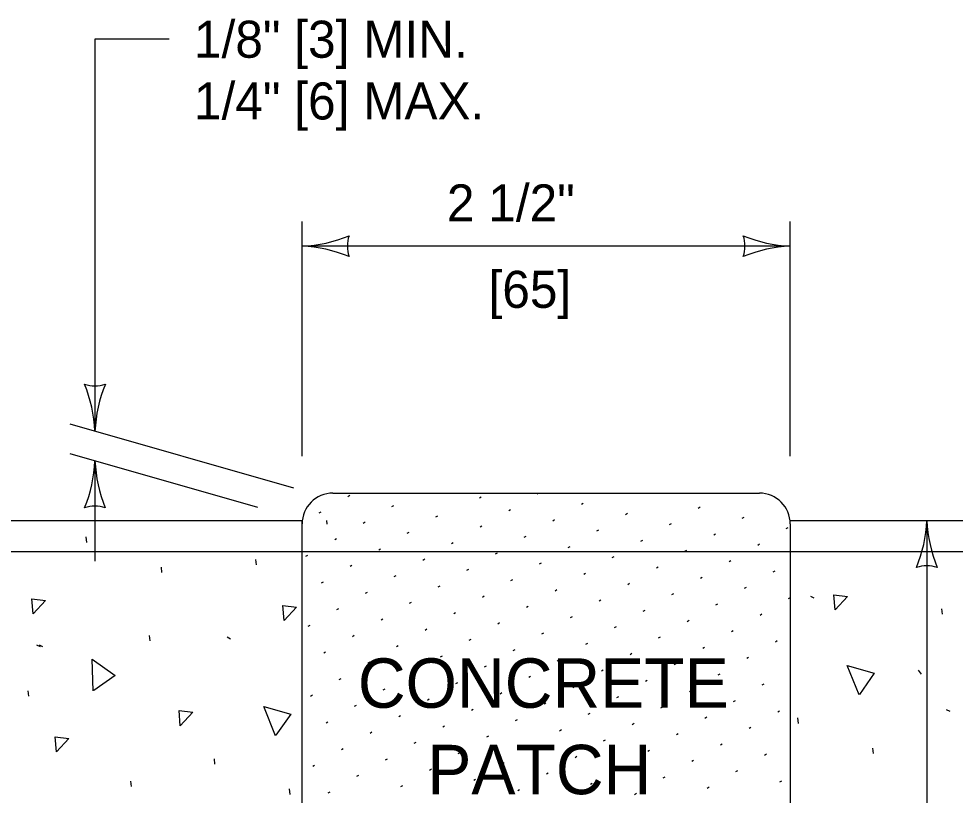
# Model space of a CAD drawing. Extents: x 49991.4 to 50021, y 49987.6 to 50011.4.
# Drawn here: x 50003.117 to 50004.633, y 49990.433 to 49991.691 of the extents above; entities that cross this region are included whole.
import ezdxf

# ---------------------------------------------------------------- set-up
doc = ezdxf.new("R2010")
doc.units = 0
for name, color, linetype in [('Level 1', 7, 'Continuous'), ('Level 15', 7, 'Continuous'), ('Level 2', 7, 'Continuous'), ('Level 3', 7, 'Continuous'), ('Level 4', 7, 'Continuous'), ('Level 6', 7, 'Continuous')]:
    doc.layers.add(name, color=color, linetype=linetype)

msp = doc.modelspace()

# ---------------------------------------------------------------- linework, layer by layer
at = {"layer": 'Level 1'}
for p, q in [((50002.5169, 49990.8781), (50003.5758, 49990.8781)), ((50004.3657, 49990.8781), (50005.421, 49990.8781)), ((50002.5169, 49990.8281), (50005.421, 49990.8281))]:
    msp.add_line(p, q, dxfattribs=at)
at = {"layer": 'Level 15'}
msp.add_line((50004.587, 49990.8781), (50004.587, 49989.7448), dxfattribs=at)
at = {"layer": 'Level 3'}
for p, q in [((50003.2406, 49991.6576), (50003.2406, 49991.0229)), ((50003.3609, 49991.6576), (50003.2406, 49991.6576)), ((50003.5758, 49990.9825), (50003.5758, 49991.3625)), ((50004.366, 49990.9825), (50004.366, 49991.3625)), ((50004.366, 49991.3225), (50003.5758, 49991.3225)), ((50003.5623, 49990.9305), (50003.2006, 49991.0344)), ((50003.5042, 49990.899), (50003.2006, 49990.9862)), ((50003.2406, 49990.9724), (50003.2406, 49990.8124)), ((50003.6499, 49990.9172), (50003.6529, 49990.919)), ((50003.8629, 49990.9148), (50003.8659, 49990.9165)), ((50003.9566, 49990.9211), (50003.959, 49990.9225)), ((50003.7212, 49990.9007), (50003.7243, 49990.9024)), ((50004.0279, 49990.9046), (50004.031, 49990.9063)), ((50004.217, 49990.8982), (50004.22, 49990.9)), ((50003.6036, 49990.8905), (50003.6066, 49990.8922)), ((50003.7926, 49990.8841), (50003.7956, 49990.8859)), ((50003.9103, 49990.8943), (50003.9133, 49990.8961)), ((50004.0993, 49990.888), (50004.1023, 49990.8898)), ((50004.2883, 49990.8817), (50004.2913, 49990.8834)), ((50003.6749, 49990.8739), (50003.6779, 49990.8757)), ((50003.8639, 49990.8676), (50003.867, 49990.8693)), ((50003.9816, 49990.8778), (50003.9846, 49990.8795)), ((50004.1706, 49990.8715), (50004.1736, 49990.8732)), ((50003.7462, 49990.8574), (50003.7493, 49990.8591)), ((50003.9353, 49990.851), (50003.9383, 49990.8528)), ((50004.0529, 49990.8613), (50004.056, 49990.863)), ((50004.242, 49990.8549), (50004.245, 49990.8567)), ((50004.3596, 49990.8651), (50004.3627, 49990.8669)), ((50003.6286, 49990.8472), (50003.6316, 49990.8489)), ((50003.8176, 49990.8408), (50003.8206, 49990.8426)), ((50004.1243, 49990.8447), (50004.1273, 49990.8465)), ((50004.3133, 49990.8384), (50004.3163, 49990.8401)), ((50003.5822, 49990.8204), (50003.5853, 49990.8222)), ((50003.6999, 49990.8306), (50003.7029, 49990.8324)), ((50003.8889, 49990.8243), (50003.892, 49990.826)), ((50004.0066, 49990.8345), (50004.0096, 49990.8362)), ((50004.1956, 49990.8282), (50004.1986, 49990.8299)), ((50003.7712, 49990.8141), (50003.7743, 49990.8158)), ((50003.9603, 49990.8077), (50003.9633, 49990.8095)), ((50004.0779, 49990.818), (50004.081, 49990.8197)), ((50004.267, 49990.8116), (50004.27, 49990.8134)), ((50003.6536, 49990.8039), (50003.6566, 49990.8056)), ((50003.8426, 49990.7975), (50003.8456, 49990.7993)), ((50004.0316, 49990.7912), (50004.0346, 49990.7929)), ((50004.1493, 49990.8014), (50004.1523, 49990.8032)), ((50004.3383, 49990.7951), (50004.3413, 49990.7968)), ((50003.6072, 49990.7771), (50003.6103, 49990.7789)), ((50003.7249, 49990.7873), (50003.7279, 49990.7891)), ((50003.9139, 49990.781), (50003.917, 49990.7827)), ((50004.1029, 49990.7746), (50004.106, 49990.7764)), ((50004.2206, 49990.7849), (50004.2236, 49990.7866)), ((50003.6786, 49990.7606), (50003.6816, 49990.7623)), ((50003.7962, 49990.7708), (50003.7993, 49990.7725)), ((50003.9853, 49990.7644), (50003.9883, 49990.7662)), ((50004.292, 49990.7683), (50004.295, 49990.7701)), ((50003.8676, 49990.7542), (50003.8706, 49990.756)), ((50004.0566, 49990.7479), (50004.0596, 49990.7496)), ((50004.1743, 49990.7581), (50004.1773, 49990.7599)), ((50004.3633, 49990.7518), (50004.3654, 49990.753)), ((50003.6322, 49990.7338), (50003.6353, 49990.7356)), ((50003.7499, 49990.744), (50003.7529, 49990.7458)), ((50003.9389, 49990.7377), (50003.942, 49990.7394)), ((50004.1279, 49990.7313), (50004.131, 49990.7331)), ((50004.2456, 49990.7416), (50004.2486, 49990.7433)), ((50003.7036, 49990.7173), (50003.7066, 49990.719)), ((50003.8212, 49990.7275), (50003.8243, 49990.7292)), ((50004.0103, 49990.7211), (50004.0133, 49990.7229)), ((50004.1993, 49990.7148), (50004.2023, 49990.7166)), ((50004.317, 49990.725), (50004.32, 49990.7268)), ((50003.7749, 49990.7007), (50003.7779, 49990.7025)), ((50003.8926, 49990.7109), (50003.8956, 49990.7127)), ((50004.0816, 49990.7046), (50004.0846, 49990.7063)), ((50003.6572, 49990.6905), (50003.6603, 49990.6923)), ((50003.8462, 49990.6842), (50003.8493, 49990.6859)), ((50003.9639, 49990.6944), (50003.967, 49990.6961)), ((50004.1529, 49990.688), (50004.156, 49990.6898)), ((50004.2706, 49990.6983), (50004.2736, 49990.7)), ((50003.7286, 49990.674), (50003.7316, 49990.6757)), ((50004.0353, 49990.6778), (50004.0383, 49990.6796)), ((50004.2243, 49990.6715), (50004.2273, 49990.6732)), ((50004.342, 49990.6817), (50004.345, 49990.6835)), ((50003.6109, 49990.6638), (50003.6139, 49990.6655)), ((50003.7999, 49990.6574), (50003.8029, 49990.6592)), ((50003.9176, 49990.6676), (50003.9206, 49990.6694)), ((50004.1066, 49990.6613), (50004.1096, 49990.663)), ((50004.2956, 49990.655), (50004.2986, 49990.6567)), ((50003.6822, 49990.6472), (50003.6853, 49990.649)), ((50003.8712, 49990.6409), (50003.8743, 49990.6426)), ((50003.9889, 49990.6511), (50003.992, 49990.6528)), ((50004.1779, 49990.6447), (50004.181, 49990.6465)), ((50003.7536, 49990.6307), (50003.7566, 49990.6324)), ((50003.9426, 49990.6243), (50003.9456, 49990.6261)), ((50004.0603, 49990.6345), (50004.0633, 49990.6363)), ((50004.2493, 49990.6282), (50004.2523, 49990.6299)), ((50003.6359, 49990.6205), (50003.6389, 49990.6222)), ((50003.8249, 49990.6141), (50003.8279, 49990.6159)), ((50004.1316, 49990.618), (50004.1346, 49990.6197)), ((50004.3206, 49990.6117), (50004.3236, 49990.6134)), ((50003.5896, 49990.5937), (50003.5926, 49990.5955)), ((50003.7072, 49990.6039), (50003.7103, 49990.6057)), ((50003.8962, 49990.5976), (50003.8993, 49990.5993)), ((50004.0139, 49990.6078), (50004.017, 49990.6095)), ((50004.2029, 49990.6014), (50004.206, 49990.6032)), ((50003.7786, 49990.5874), (50003.7816, 49990.5891)), ((50003.9676, 49990.581), (50003.9706, 49990.5828)), ((50004.0853, 49990.5912), (50004.0883, 49990.593)), ((50004.2743, 49990.5849), (50004.2773, 49990.5866)), ((50003.6609, 49990.5772), (50003.6639, 49990.5789)), ((50003.8499, 49990.5708), (50003.8529, 49990.5726)), ((50004.0389, 49990.5645), (50004.042, 49990.5662)), ((50004.1566, 49990.5747), (50004.1596, 49990.5764)), ((50004.3456, 49990.5683), (50004.3486, 49990.5701)), ((50003.6146, 49990.5504), (50003.6176, 49990.5522)), ((50003.7322, 49990.5606), (50003.7353, 49990.5624)), ((50003.9212, 49990.5543), (50003.9243, 49990.556)), ((50004.1103, 49990.5479), (50004.1133, 49990.5497)), ((50004.2279, 49990.5581), (50004.231, 49990.5599)), ((50003.6859, 49990.5339), (50003.6889, 49990.5356)), ((50003.8036, 49990.5441), (50003.8066, 49990.5458)), ((50003.9926, 49990.5377), (50003.9956, 49990.5395)), ((50004.2993, 49990.5416), (50004.3023, 49990.5433)), ((50003.7572, 49990.5173), (50003.7603, 49990.5191)), ((50003.8749, 49990.5275), (50003.8779, 49990.5293)), ((50004.0639, 49990.5212), (50004.067, 49990.5229)), ((50004.1816, 49990.5314), (50004.1846, 49990.5331)), ((50003.6396, 49990.5071), (50003.6426, 49990.5089)), ((50003.9462, 49990.511), (50003.9493, 49990.5127)), ((50004.1353, 49990.5046), (50004.1383, 49990.5064)), ((50004.2529, 49990.5148), (50004.256, 49990.5166)), ((50003.7109, 49990.4906), (50003.7139, 49990.4923)), ((50003.8286, 49990.5008), (50003.8316, 49990.5025)), ((50004.0176, 49990.4944), (50004.0206, 49990.4962)), ((50004.2066, 49990.4881), (50004.2096, 49990.4898)), ((50004.3243, 49990.4983), (50004.3273, 49990.5)), ((50003.5932, 49990.4804), (50003.5962, 49990.4821)), ((50003.7822, 49990.474), (50003.7853, 49990.4758)), ((50003.8999, 49990.4842), (50003.9029, 49990.486)), ((50004.0889, 49990.4779), (50004.092, 49990.4796)), ((50004.2779, 49990.4715), (50004.281, 49990.4733)), ((50003.6646, 49990.4638), (50003.6676, 49990.4656)), ((50003.8536, 49990.4575), (50003.8566, 49990.4592)), ((50003.9712, 49990.4677), (50003.9743, 49990.4694)), ((50004.1603, 49990.4613), (50004.1633, 49990.4631)), ((50003.7359, 49990.4473), (50003.7389, 49990.449)), ((50004.0426, 49990.4511), (50004.0456, 49990.4529)), ((50004.2316, 49990.4448), (50004.2346, 49990.4465)), ((50004.3493, 49990.455), (50004.3523, 49990.4567)), ((50003.6182, 49990.4371), (50003.6212, 49990.4388)), ((50003.9249, 49990.4409), (50003.9279, 49990.4427)), ((50004.1139, 49990.4346), (50004.117, 49990.4363))]:
    msp.add_line(p, q, dxfattribs=at)
for centre, radius, start, end in [((50003.5667, 49991.5446), 0.2223, 272.3613, 292.5448), ((50003.704, 49991.3225), 0.0548, 162.1396, 197.862), ((50004.3752, 49991.5446), 0.2223, 247.4552, 267.6387), ((50004.2378, 49991.3225), 0.0548, 342.138, 17.8604), ((50003.5643, 49991.0898), 0.233, 67.9236, 87.1735), ((50004.3775, 49991.0898), 0.233, 92.8265, 112.0764), ((50003.2406, 49991.1511), 0.0548, 252.1388, 287.8612), ((50003.0079, 49991.0114), 0.233, 2.8273, 22.0772), ((50003.4628, 49991.0138), 0.2223, 157.456, 177.6395), ((50003.0185, 49990.9839), 0.2223, 337.456, 357.6395), ((50003.4733, 49990.9862), 0.233, 182.8273, 202.0772), ((50003.2406, 49990.8465), 0.0548, 72.1388, 107.8612), ((50004.3649, 49990.8873), 0.2223, 337.456, 357.6395), ((50004.8197, 49990.8896), 0.233, 182.8273, 202.0772), ((50004.587, 49990.7499), 0.0548, 72.1388, 107.8612)]:
    msp.add_arc(centre, radius, start, end, dxfattribs=at)
at = {"layer": 'Level 4'}
for p, q in [((50003.6163, 49990.8721), (50003.6157, 49990.8781)), ((50003.2275, 49990.8427), (50003.2266, 49990.8514)), ((50003.5019, 49990.8061), (50003.501, 49990.8148)), ((50003.349, 49990.7939), (50003.3481, 49990.8026)), ((50004.3986, 49990.7556), (50004.4043, 49990.7528)), ((50004.6124, 49990.7263), (50004.6115, 49990.735)), ((50003.3298, 49990.6832), (50003.3289, 49990.6919)), ((50003.4544, 49990.6895), (50003.4601, 49990.6867)), ((50003.146, 49990.6767), (50003.1517, 49990.6738)), ((50003.1501, 49990.6767), (50003.1558, 49990.6738)), ((50004.5731, 49990.6358), (50004.5779, 49990.6294)), ((50003.1335, 49990.5935), (50003.1326, 49990.6022)), ((50004.6185, 49990.5721), (50004.6242, 49990.5693)), ((50004.3791, 49990.5496), (50004.3782, 49990.5583)), ((50004.5006, 49990.5008), (50004.4997, 49990.5095)), ((50003.4349, 49990.4835), (50003.434, 49990.4921)), ((50003.2998, 49990.4475), (50003.2989, 49990.4562)), ((50003.5564, 49990.4346), (50003.5555, 49990.4433))]:
    msp.add_line(p, q, dxfattribs=at)
for points in [[(50003.1406, 49990.7269), (50003.1387, 49990.7514), (50003.1607, 49990.7488), (50003.1406, 49990.7269)], [(50004.4384, 49990.7334), (50004.4366, 49990.758), (50004.4586, 49990.7553), (50004.4384, 49990.7334)], [(50003.5467, 49990.7161), (50003.5448, 49990.7407), (50003.5668, 49990.738), (50003.5467, 49990.7161)], [(50003.238, 49990.6025), (50003.2361, 49990.6537), (50003.2731, 49990.6269), (50003.2388, 49990.603)], [(50004.4773, 49990.5956), (50004.458, 49990.6431), (50004.5019, 49990.6306), (50004.4778, 49990.5963)], [(50003.3786, 49990.5458), (50003.3767, 49990.5704), (50003.3988, 49990.5677), (50003.3786, 49990.5458)], [(50003.5331, 49990.5295), (50003.5138, 49990.577), (50003.5578, 49990.5644), (50003.5336, 49990.5302)], [(50003.1783, 49990.5034), (50003.1764, 49990.528), (50003.1985, 49990.5253), (50003.1783, 49990.5034)]]:
    msp.add_lwpolyline(points, dxfattribs=at)
at = {"layer": 'Level 6'}
for p, q in [((50003.6258, 49990.9225), (50004.316, 49990.9225)), ((50003.5758, 49989.9969), (50003.5758, 49990.8781)), ((50004.366, 49990.8725), (50004.366, 49989.9969)), ((50003.5859, 49990.7071), (50003.5889, 49990.7088))]:
    msp.add_line(p, q, dxfattribs=at)
for centre, start, end in [((50003.6258, 49990.8725), 90, 180), ((50004.316, 49990.8725), 0, 90)]:
    msp.add_arc(centre, 0.05, start, end, dxfattribs=at)

# ---------------------------------------------------------------- texts
at = {"layer": 'Level 2'}
for s, height, p in [('1/8" [3] MIN.', 0.06, (50003.4009, 49991.6276)), ('1/4" [6] MAX.', 0.06, (50003.4009, 49991.5276)), ('2 1/2"', 0.06, (50003.8103, 49991.3625)), ('[65]', 0.06, (50003.8776, 49991.2225)), ('CONCRETE', 0.08, (50003.6661, 49990.5748)), ('PATCH', 0.08, (50003.7785, 49990.4348))]:
    msp.add_text(s, height=height, dxfattribs=at).set_placement(p)

doc.saveas('drawing.dxf')
